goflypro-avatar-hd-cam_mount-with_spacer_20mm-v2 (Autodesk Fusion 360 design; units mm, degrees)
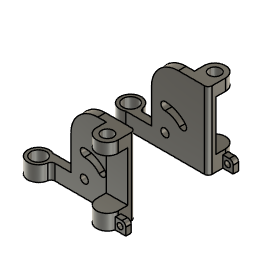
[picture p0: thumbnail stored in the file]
sketch "Skizze1" plane through (0, 0, 0) normal (0, 0, 1) x axis (1, 0, 0)
  line L1 (7.2, 0.5) -> (-7.2, 0.5)
  line L2 (7.2, 0.5) -> (7.2, -2)
  line L3 (-2, 0.5) -> (-2, 2.5)
  line L4 (12.8, 2.5) -> (-8.6926, 2.5)
  line L5 (12.8, 2.5) -> (12.8, -2)
  line L6 (12.8, 0.5) -> (7.2, 0.5)
  line L7 (11, -2) -> (11, 2.5)
  line L8 (12.8, -2) -> (11, -2)
  circle C1 centre (-9.9551, 0.0008) radius 2
  circle C2 centre (10, -2) radius 1.55
  circle C3 centre (-9.9551, 0.0008) radius 2.8
  circle C4 centre (10, -2) radius 2.8
  point P6 (-7.2, 0.5)
  point P7 (7.2, -2)
  point P10 (-2, 0.5)
  point P12 (12.8, -2)
  point P15 (11, 2.5)
  point P11 (-8.6926, 2.5)
  point P9 (-2, 2.5)
  point P14 (12.8, 0.5)
  concentric C1 C3
  concentric C2 C4
  coincident C3 P6
  coincident C4 P7
  coincident L1 P10
  coincident C4 P12
  coincident L4 P15
  coincident C3 P11
  horizontal L4
  coincident P9 L4
  perpendicular L3 L4
  coincident L5 P14
  perpendicular L5 L6
  dimension "d1" diameter C1 = 4
  dimension "d2" diameter C2 = 3.1
  dimension "d3" diameter C3 = 5.6
  dimension "d4" diameter C4 = 5.6
extrude "Extrusion1" new body sketch "Skizze1" profile of C1 C3 L1 L3 L4 along normal blind 4 bodies "GoFlyPro - Avatar-HD-cam mount with spacer 20mm - left"
extrude "Extrusion5" new body sketch "Skizze1" profile of C2 C4 L2 L5 L6 L7 L8 along normal blind 4 bodies "GoFlyPro - Avatar-HD-cam mount with spacer 20mm - left"
extrude "Extrusion8" add sketch "Skizze1" profile of C4 L1 L3 L4 L5 L6 L7 along normal blind 20 bodies "GoFlyPro - Avatar-HD-cam mount with spacer 20mm - left"
sketch "Skizze2" plane through (0, 0.5, 0) normal (0, 1, 0) x axis (1, 0, 0)
  line L1 (7.2, 0) -> (-7.2, 0)
  line L2 (7.2, -4) -> (7.2, 0)
  line L3 (7.2, -20) -> (7.2, -4)
  line L4 (-2, -20) -> (7.2, -20)
  line L5 (-2, -4) -> (-2, -20)
  line L6 (-7.2, -4) -> (-2, -4)
  line L7 (-7.2, 0) -> (-7.2, -4)
  circle C1 centre (1.5, -4.25) radius 1.05
  circle C2 centre (1.5, -4.25) radius 4.95
  circle C3 centre (1.5, -4.25) radius 7.05
  circle C4 centre (1.5, -10.25) radius 1.05
  circle C5 centre (6.0963, -8.1067) radius 1.05
  concentric C1 C2
  concentric C2 C3
  dimension "d8" diameter C1 = 2.1
  dimension "d32" diameter C4 = 2.1
  dimension "d64" diameter C5 = 2.1
extrude "Extrusion2" cut sketch "Skizze2" profile of C1 C2 C3 C4 C5 L3 along normal blind 2
fillet "Abrundung12" radius 1
work_plane "Arbeitsebene" AlongDistance 12
sketch "Skizze3" plane through (0, 0, 20) normal (0, 0, 1) x axis (-1, 0, 0)
  line L1 (-12.8, -2) -> (-12.8, 2)
  line L2 (-7, -2) -> (-12.8, -2)
  line L3 (-7, 0) -> (-7, -2)
  line L4 (-7.2, 0) -> (-7, 0)
  line L5 (-11.9596, 0) -> (-7.2, 0)
  line L6 (2, -0.5) -> (2, -2.5)
  line L7 (-7.2, -0.5) -> (2, -0.5)
  line L8 (-12.8, -0.5) -> (-7.2, -0.5)
  line L9 (-12.8, -2.5) -> (-12.8, -0.5)
  line L10 (2, -2.5) -> (-12.8, -2.5)
  line L11 (-11.9596, 0) -> (-12.8, -0.5)
  line L12 (-12.8, 2) -> (-12.8, -0.5)
  line L13 (-8.0404, 0) -> (-7.2, -0.5)
  line L14 (-7.2, 2) -> (-7.2, -0.5)
  line L15 (-12.8, -0.5) -> (-7.2, -0.5)
  line L16 (-12.8, 2) -> (-12.8, -0.5)
  circle C1 centre (-10, 2) radius 1.55
  circle C2 centre (-10, 2) radius 2.8
  arc A1 centre (-10, 2) radius 2.8 clockwise from (-11.9596, 0) to (-12.8, 2)
  point P14 (-12.8, -0.5)
  point P16 (-12.8, -0.5)
  point P2 (-11.9596, 0)
  point P17 (-11.9596, 0)
  point P18 (-12.8, -0.5)
  point P3 (-12.8, 2)
  point P19 (-12.8, 2)
  point P13 (-7.2, -0.5)
  point P20 (-7.2, -0.5)
  point P21 (-8.0404, 0)
  point P22 (-7.2, -0.5)
  point P23 (-7.2, 2)
  concentric C1 C2
  coincident P14 P16
  coincident P2 P17
  coincident P14 P18
  coincident P3 P19
  coincident P13 P20
  coincident C2 P21
  coincident L5 P21
  coincident P13 P22
  coincident C2 P23
  tangent C2 L14
  dimension "d77" diameter C1 = 3.1
  dimension "d78" diameter C2 = 5.6
extrude "Extrusion10" add sketch "Skizze3" profile of L1 C1 C2 L5 A1 L8 L11 L12 L13 L14 L15 L16 against normal blind 3
extrude "Extrusion11" cut sketch "Skizze1" profile of C2 L7 L8 along normal blind 3.2
extrude "Extrusion12" cut sketch "Skizze3" profile of C1 against normal blind 3
fillet "Abrundung23" radius 7
fillet "Abrundung24" radius 1
sketch "Skizze4" plane through (0, 0, 0) normal (0, 0, 1) x axis (1, 0, 0)
  line L1 (12.5, -2.7) -> (15.5, -2.7)
  line L2 (12.5, -1.3) -> (12.5, -2.7)
  line L3 (15.5, -1.3) -> (12.5, -1.3)
  line L4 (15.5, -2.7) -> (15.5, -1.3)
  horizontal L1
  vertical L2
  horizontal L3
  vertical L4
extrude "Extrusion13" add sketch "Skizze4" along normal blind 3
sketch "Skizze5" plane through (0, -2.7, 0) normal (0, -1, 0) x axis (1, 0, 0)
  line L1 (15.5, 0) -> (12.7111, 0)
  line L2 (15.5, 3) -> (15.5, 0)
  line L3 (12.7111, 3) -> (15.5, 3)
  line L4 (12.7111, 0) -> (12.7111, 3)
  circle C1 centre (14, 1.5) radius 0.75
  dimension "d93" diameter C1 = 1.5
extrude "Extrusion14" cut sketch "Skizze5" profile of C1 against normal blind 1.4
fillet "Abrundung22" radius 1
mirror "Spiegeln" mirrorStitchTolerance 0.1 bodies "GoFlyPro - Avatar-HD-cam mount with spacer 20mm - right"
named bodies: "GoFlyPro - Avatar-HD-cam mount with spacer 20mm - left", "GoFlyPro - Avatar-HD-cam mount with spacer 20mm - right"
